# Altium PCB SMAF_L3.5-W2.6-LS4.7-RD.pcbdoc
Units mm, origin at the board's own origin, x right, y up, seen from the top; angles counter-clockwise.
Board outline 18.22 x 15.55 mm, 2 copper layers (Top Layer, Bottom Layer), stack 0 mm thick; 1 components, 0 nets, 2 pads, 0 vias.
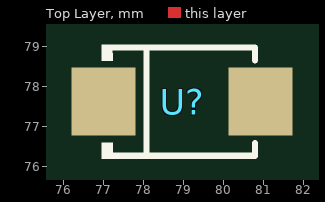
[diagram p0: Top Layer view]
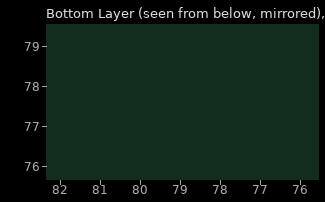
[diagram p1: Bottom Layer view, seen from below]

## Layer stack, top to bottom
Top Layer: signal copper (thickness not stored)
Bottom Layer: signal copper (thickness not stored)

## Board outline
88.07,69.85 69.85,69.85 69.85,85.4 88.07,85.4

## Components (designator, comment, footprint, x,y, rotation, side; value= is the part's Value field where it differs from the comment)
U? "" SMAF_L3.5-W2.6-LS4.7-RD 78.96,77.63 r0 top

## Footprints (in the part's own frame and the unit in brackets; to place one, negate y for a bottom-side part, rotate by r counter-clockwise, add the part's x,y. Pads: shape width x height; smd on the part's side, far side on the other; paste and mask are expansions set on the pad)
SMAF_L3.5-W2.6-LS4.7-RD [mm]
  rect 1.6x1.7 smd: 1(-1.96,0) 2(1.96,0)
  silkscreen extent -2.01,-1.43 1.83,1.42

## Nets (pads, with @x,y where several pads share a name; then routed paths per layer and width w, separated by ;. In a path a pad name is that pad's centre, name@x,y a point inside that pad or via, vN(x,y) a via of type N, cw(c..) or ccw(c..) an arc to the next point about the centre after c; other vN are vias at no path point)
pads on no net: U?.1 U?.2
